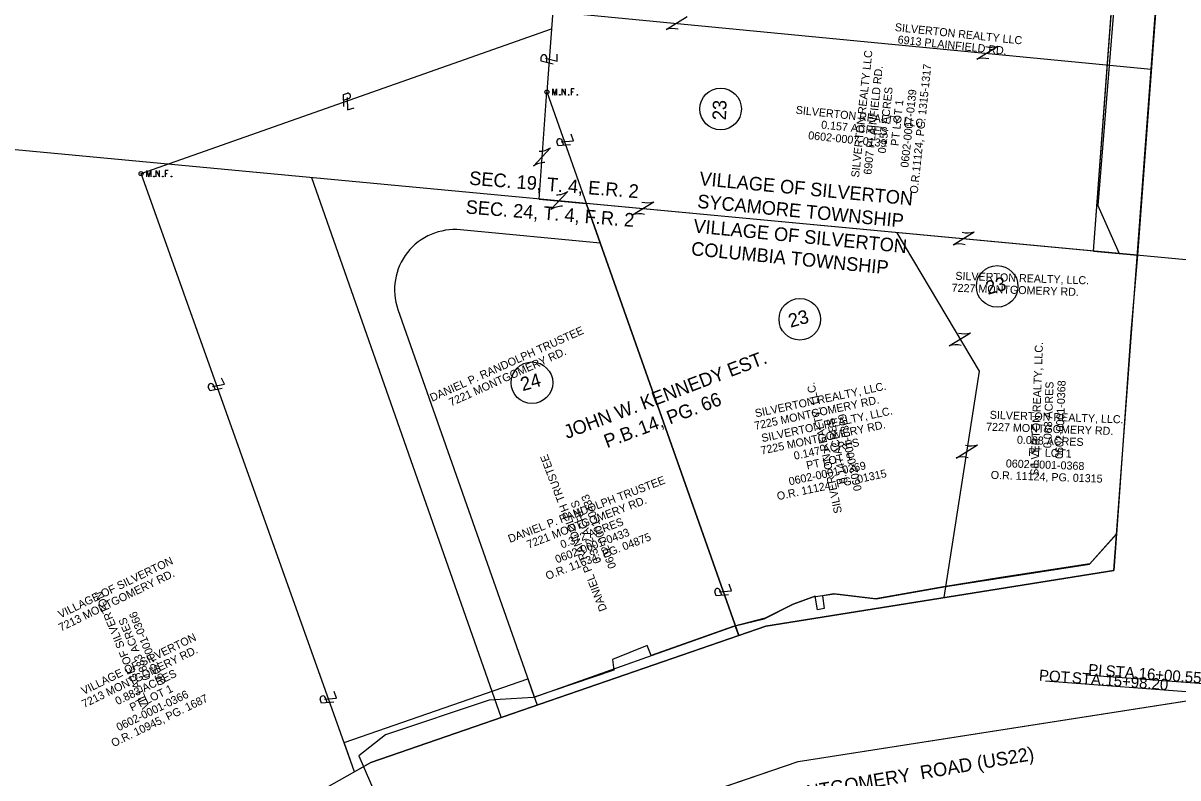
# Model space of a CAD drawing. Extents: x 204354 to 231038, y 361459 to 365260.
# Drawn here: x 220261.9 to 220550.5, y 362138.8 to 362327.5 of the extents above; entities that cross this region are included whole.
import ezdxf

# ---------------------------------------------------------------- set-up
doc = ezdxf.new("R2010")
doc.units = 0
for name, color, linetype in [('CM_Corridor_Point_Control', 7, 'Continuous'), ('CM_Corridor_Range_Conceptual', 7, 'Continuous'), ('DT_P_Contour_Minor', 7, 'Continuous'), ('DT_P_Contour_Text', 7, 'Continuous'), ('DT_P_Tie', 7, 'Continuous'), ('DT_P_Triangles', 7, 'Continuous'), ('DT_P_Void', 7, 'Continuous'), ('DT_X_Contour_Minor', 7, 'Continuous'), ('MD_P_AGB_B', 7, 'Continuous'), ('MD_P_CURB_FACE_TOP', 7, 'Continuous'), ('MD_P_Intersection_MatchLine', 7, 'Continuous'), ('MD_P_Surface_Asphalt_Concrete_Base', 7, 'Continuous'), ('MD_P_SW_BOT', 7, 'Continuous'), ('MD_P_SW_TOP', 7, 'Continuous'), ('PV_P_Walk', 7, 'Continuous'), ('SC_Shading1', 7, 'Continuous'), ('SH_Text', 7, 'Continuous')]:
    doc.layers.add(name, color=color, linetype=linetype)

msp = doc.modelspace()

# ---------------------------------------------------------------- linework, layer by layer
at = {"layer": 'CM_Corridor_Range_Conceptual'}
for p, q in [((220455.61, 362142.97), (221144.38, 362250.6)), ((220361, 362110.59), (220455.61, 362142.97))]:
    msp.add_line(p, q, dxfattribs=at)
msp.add_lwpolyline([(219371.89, 361640.54), (220361, 362110.59), (220455.61, 362142.97), (221144.38, 362250.6)], dxfattribs=at)
at = {"layer": 'DT_P_Contour_Text'}
for centre in [(220436.22, 362306.05), (220505.32, 362261.7), (220456.01, 362253.48), (220389.08, 362237.62)]:
    msp.add_circle(centre, 5.2, dxfattribs=at)
at = {"layer": 'DT_P_Tie'}
for p, q in [((220381.43, 362154.05), (220334.09, 362288.87)), ((220406.15, 362272.49), (220371.25, 362275.82)), ((220355.61, 362255.92), (220390.35, 362157))]:
    msp.add_line(p, q, dxfattribs=at)
msp.add_arc((220369.76, 362260.89), 15, 84.2977, 199.3503, dxfattribs=at)
at = {"layer": 'DT_P_Triangles'}
msp.add_lwpolyline([(220536.18, 362353), (220530.49, 362281.93), (220535.8, 362269.9), (220540.35, 362269.47), (220538.74, 362250.25), (220535.12, 362199.8), (220528.47, 362192.34), (220506.26, 362188.94), (220491.95, 362186.6), (220474.95, 362183.6), (220464.5, 362184.86), (220461.66, 362184.35), (220462.06, 362181.15), (220460.42, 362180.88), (220459.81, 362184.23), (220454.36, 362182.28), (220447.35, 362178.73), (220439.37, 362176.7), (220418.89, 362169.4), (220417.87, 362171.93), (220409.17, 362168.46), (220409.53, 362165.73), (220389.36, 362158.93), (220378.39, 362158.25), (220352.47, 362149.63), (220345.8, 362144.38), (220374.43, 362078.2)], dxfattribs=at)
at = {"layer": 'MD_P_AGB_B'}
msp.add_line((220572.38, 362161.22), (220527.51, 362164.56), dxfattribs=at)
at = {"layer": 'MD_P_CURB_FACE_TOP'}
msp.add_line((220562.24, 362159.63), (220517.36, 362162.98), dxfattribs=at)
at = {"layer": 'MD_P_Intersection_MatchLine'}
for p, q in [((220529.39, 362270.5), (220536.83, 362370.22)), ((220529.39, 362270.5), (220536.83, 362370.21)), ((220529.39, 362270.5), (220540.35, 362269.47)), ((220388.03, 362163.6), (220390.35, 362157))]:
    msp.add_line(p, q, dxfattribs=at)
at = {"layer": 'MD_P_Surface_Asphalt_Concrete_Base'}
for points in [[(220394.26, 362309.48), (220394.26, 362311.08), (220394.77, 362309.48), (220395.25, 362311.08), (220395.25, 362309.48)], [(220396.63, 362309.48), (220396.63, 362311.08), (220397.46, 362309.48), (220397.46, 362311.08)], [(220399.61, 362311.08), (220398.84, 362311.08), (220398.84, 362309.48)], [(220396.02, 362309.69), (220396.08, 362309.69), (220396.11, 362309.67), (220396.14, 362309.62), (220396.14, 362309.56), (220396.11, 362309.51), (220396.08, 362309.48), (220396.02, 362309.48), (220395.99, 362309.51), (220395.96, 362309.56), (220395.96, 362309.62), (220395.99, 362309.67), (220396.02, 362309.69)], [(220398.24, 362309.69), (220398.29, 362309.69), (220398.33, 362309.67), (220398.36, 362309.62), (220398.36, 362309.56), (220398.33, 362309.51), (220398.29, 362309.48), (220398.24, 362309.48), (220398.21, 362309.51), (220398.17, 362309.56), (220398.17, 362309.62), (220398.21, 362309.67), (220398.24, 362309.69)], [(220398.84, 362310.3), (220399.39, 362310.3)], [(220400.39, 362309.69), (220400.44, 362309.69), (220400.48, 362309.67), (220400.51, 362309.62), (220400.51, 362309.56), (220400.48, 362309.51), (220400.44, 362309.48), (220400.39, 362309.48), (220400.35, 362309.51), (220400.32, 362309.56), (220400.32, 362309.62), (220400.35, 362309.67), (220400.39, 362309.69)], [(220292.84, 362289.08), (220292.84, 362290.68), (220293.35, 362289.08), (220293.83, 362290.68), (220293.83, 362289.08)], [(220294.61, 362289.29), (220294.66, 362289.29), (220294.69, 362289.27), (220294.73, 362289.22), (220294.73, 362289.16), (220294.69, 362289.11), (220294.66, 362289.08), (220294.61, 362289.08), (220294.57, 362289.11), (220294.54, 362289.16), (220294.54, 362289.22), (220294.57, 362289.27), (220294.61, 362289.29)], [(220295.21, 362289.08), (220295.21, 362290.68), (220296.04, 362289.08), (220296.04, 362290.68)], [(220296.82, 362289.29), (220296.88, 362289.29), (220296.91, 362289.27), (220296.94, 362289.22), (220296.94, 362289.16), (220296.91, 362289.11), (220296.88, 362289.08), (220296.82, 362289.08), (220296.79, 362289.11), (220296.75, 362289.16), (220296.75, 362289.22), (220296.79, 362289.27), (220296.82, 362289.29)], [(220298.19, 362290.68), (220297.43, 362290.68), (220297.43, 362289.08)], [(220297.43, 362289.9), (220297.97, 362289.9)], [(220298.97, 362289.29), (220299.03, 362289.29), (220299.06, 362289.27), (220299.09, 362289.22), (220299.09, 362289.16), (220299.06, 362289.11), (220299.03, 362289.08), (220298.97, 362289.08), (220298.94, 362289.11), (220298.9, 362289.16), (220298.9, 362289.22), (220298.94, 362289.27), (220298.97, 362289.29)]]:
    msp.add_lwpolyline(points, dxfattribs=at)
for centre in [(220392.82, 362310.29), (220291.4, 362289.89)]:
    msp.add_circle(centre, 0.497, dxfattribs=at)
at = {"layer": 'MD_P_SW_BOT'}
for p, q in [((220398.11, 362383.18), (220392.82, 362310.29)), ((220394.27, 362330.37), (220543.82, 362315.97)), ((220422.58, 362325.89), (220427.9, 362329.17)), ((220500.2, 362318.48), (220505.52, 362321.76)), ((220502.86, 362320.12), (220502.86, 362320.12)), ((220392.79, 362317.65), (220392.76, 362318.95)), ((220393.39, 362318.47), (220393.39, 362318.47)), ((220342.01, 362308.27), (220343.25, 362308.64)), ((220390.91, 362283.53), (220392.82, 362310.29)), ((220392.82, 362310.29), (220440.76, 362174.4)), ((220342.96, 362307.9), (220342.96, 362307.9)), ((220397.08, 362296.94), (220396.64, 362298.16)), ((220397.4, 362297.9), (220397.4, 362297.9)), ((220389.44, 362291.79), (220393.72, 362296.35)), ((220391.58, 362294.07), (220391.58, 362294.07)), ((220393.81, 362280.88), (220398.08, 362285.44)), ((220390.91, 362283.53), (220402.65, 362282.42)), ((220395.94, 362283.16), (220395.94, 362283.16)), ((220540.34, 362269.47), (220402.65, 362282.42)), ((220440.76, 362174.4), (220402.71, 362282.25)), ((220414.18, 362279.58), (220419.5, 362282.86)), ((220416.84, 362281.22), (220416.84, 362281.22)), ((220494.29, 362272.05), (220499.61, 362275.32)), ((220496.95, 362273.69), (220496.95, 362273.69)), ((220493.3, 362246.84), (220498.62, 362250.12)), ((220495.96, 362248.48), (220495.96, 362248.48)), ((220310.03, 362235.85), (220309.48, 362237.02)), ((220310.26, 362236.84), (220310.26, 362236.84)), ((220495.08, 362218.8), (220500.4, 362222.08)), ((220497.74, 362220.44), (220497.74, 362220.44)), ((220436.54, 362184.5), (220436.11, 362185.72)), ((220436.86, 362185.46), (220436.86, 362185.46)), ((220337.91, 362157.65), (220337.47, 362158.87)), ((220338.23, 362158.61), (220338.23, 362158.61))]:
    msp.add_line(p, q, dxfattribs=at)
for points in [[(220344.74, 362140.37), (220291.4, 362289.89), (220393.96, 362326.05)], [(220392.43, 362318.71), (220395.4, 362318), (220395.35, 362319.75)], [(220394.4, 362317.28), (220391.41, 362317.97), (220391.38, 362319)], [(220342.06, 362306.63), (220341.97, 362309.69), (220342.96, 362309.98)], [(220342.94, 362308.9), (220343.02, 362305.84), (220344.7, 362306.33)], [(220396.4, 362297.83), (220399.45, 362298.07), (220398.87, 362299.72)], [(220398.72, 362297.07), (220395.66, 362296.82), (220395.32, 362297.8)], [(220492.04, 362183.91), (220500.91, 362240.5), (220480.35, 362275.05)], [(220311.65, 362236.15), (220308.64, 362235.59), (220308.2, 362236.53)], [(220309.27, 362236.67), (220312.29, 362237.22), (220311.54, 362238.8)], [(220435.86, 362185.39), (220438.92, 362185.63), (220438.33, 362187.28)], [(220438.18, 362184.63), (220435.12, 362184.38), (220434.78, 362185.36)], [(220339.55, 362157.79), (220336.49, 362157.53), (220336.15, 362158.5)], [(220337.23, 362158.54), (220340.28, 362158.79), (220339.7, 362160.43)]]:
    msp.add_lwpolyline(points, dxfattribs=at)
for centre, radius, start, end in [((220424.21, 362320.81), 5.34, 75.1519, 107.7944), ((220503.89, 362326.84), 5.34, 255.1519, 287.7944), ((220392.07, 362318.92), 0.69, 2.1187, 172.9759), ((220501.84, 362313.4), 5.34, 75.1519, 107.7944), ((220343.05, 362309.3), 0.69, 286.9752, 97.8324), ((220396, 362297.92), 0.69, 19.9042, 190.7613), ((220390.81, 362300.82), 5.34, 270.3758, 303.0184), ((220392.35, 362287.31), 5.34, 90.3758, 123.0184), ((220395.17, 362289.91), 5.34, 270.3758, 303.0184), ((220417.87, 362287.94), 5.34, 255.1519, 287.7944), ((220396.72, 362276.4), 5.34, 90.3758, 123.0184), ((220415.81, 362274.5), 5.34, 75.1519, 107.7944), ((220497.97, 362280.41), 5.34, 255.1519, 287.7944), ((220495.92, 362266.96), 5.34, 75.1519, 107.7944), ((220496.99, 362255.2), 5.34, 255.1519, 287.7944), ((220494.93, 362241.76), 5.34, 75.1519, 107.7944), ((220308.86, 362236.72), 0.69, 25.7397, 196.5968), ((220498.77, 362227.16), 5.34, 255.1519, 287.7944), ((220496.71, 362213.72), 5.34, 75.1519, 107.7944), ((220435.46, 362185.49), 0.69, 19.9042, 190.7613), ((220336.83, 362158.63), 0.69, 20.1022, 190.9593)]:
    msp.add_arc(centre, radius, start, end, dxfattribs=at)
at = {"layer": 'MD_P_SW_TOP'}
msp.add_line((220580.15, 362265.73), (220066.77, 362314.01), dxfattribs=at)
at = {"layer": 'PV_P_Walk'}
for p, q in [((220534.47, 362190.67), (220633.24, 363514.5)), ((220447.51, 362176.73), (220534.47, 362190.67)), ((220348.83, 362142.66), (220447.51, 362176.73)), ((220269.85, 362098.37), (220348.83, 362142.66))]:
    msp.add_line(p, q, dxfattribs=at)
at = {"layer": 'SC_Shading1'}
for points in [[(220540.35, 362269.47), (220529.39, 362270.5), (220536.83, 362370.21), (220547.79, 362369.18)], [(220534.47, 362190.67), (220447.51, 362176.73), (220440.76, 362174.4), (220439.88, 362176.89), (220447.1, 362178.59), (220454.36, 362182.28), (220459.33, 362184.06), (220464.67, 362184.85), (220475.11, 362183.61), (220492.47, 362186.7), (220528.38, 362192.25), (220535.15, 362199.84)], [(220440.76, 362174.4), (220348.83, 362142.66), (220344.74, 362140.37), (220342.12, 362147.7), (220388.03, 362163.6), (220389.64, 362159.02), (220439.88, 362176.89)]]:
    msp.add_lwpolyline(points, close=True, dxfattribs=at)
at = {"layer": 'SH_Text'}
msp.add_lwpolyline([(220534.47, 362190.67), (220447.51, 362176.73), (220440.76, 362174.4), (220439.88, 362176.89), (220447.11, 362178.59), (220454.37, 362182.28), (220459.33, 362184.07), (220464.67, 362184.86), (220475.12, 362183.61), (220492.48, 362186.7), (220528.39, 362192.25), (220535.16, 362199.84), (220534.48, 362190.67)], dxfattribs=at)
msp.add_lwpolyline([(220534.47, 362190.67), (220447.51, 362176.73), (220440.76, 362174.4), (220439.88, 362176.89), (220447.11, 362178.59), (220454.37, 362182.28), (220459.33, 362184.07), (220464.67, 362184.86), (220475.12, 362183.61), (220492.48, 362186.7), (220528.39, 362192.25), (220535.16, 362199.84), (220534.48, 362190.67)], dxfattribs=at)
msp.add_lwpolyline([(220534.47, 362190.67), (220447.51, 362176.73), (220440.76, 362174.4), (220439.88, 362176.89), (220447.11, 362178.59), (220454.37, 362182.28), (220459.33, 362184.07), (220464.67, 362184.86), (220475.12, 362183.61), (220492.48, 362186.7), (220528.39, 362192.25), (220535.16, 362199.84), (220534.48, 362190.67)], dxfattribs=at)

# ---------------------------------------------------------------- texts
at = {"layer": 'CM_Corridor_Point_Control'}
for s, rotation, p in [('SILVERTON REALTY LLC', 353.953, (220479.69, 362325.54)), ('6913 PLAINFIELD RD.', 353.953, (220480.39, 362322.45)), ('SILVERTON REALTY, LLC.', 358, (220494.85, 362263.36)), ('7227 MONTGOMERY RD.', 358, (220493.92, 362260.39)), ('DANIEL P. RANDOLPH TRUSTEE', 24.2285, (220364.14, 362232.84)), ('7221 MONTGOMERY RD.', 24.2285, (220368.88, 362231.68)), ('SILVERTON REALTY, LLC.', 12.0129, (220445.04, 362228.95)), ('7225 MONTGOMERY RD.', 12.0129, (220444.86, 362225.85)), ('VILLAGE OF SILVERTON', 25.8749, (220271.27, 362178.68)), ('7213 MONTGOMERY RD.', 25.8749, (220271.4, 362175.41))]:
    msp.add_text(s, height=2, rotation=rotation, dxfattribs=at).set_placement(p)
at = {"layer": 'DT_P_Contour_Minor'}
for s, height, rotation, p in [('SILVERTON REALTY LLC', 2, 83.953, (220470.8, 362288.84)), ('O.R.11124, PG. 1315-1317', 2, 83.953, (220485.46, 362284.8)), ('6907 PLAINFIELD RD.', 2, 83.953, (220473.89, 362289.54)), (' 0.157 ACRES', 2, 83.953, (220477.4, 362294.13)), ('0602-0007-0139', 2, 83.953, (220483.13, 362291.32)), ('PT LOT 1', 2, 83.953, (220480.69, 362296.72)), ('SEC. 19, T. 4, E.R. 2', 3.4, 355.407, (220373.3, 362287.13)), ('VILLAGE OF SILVERTON', 3.4, 354.5316, (220430.81, 362287.02)), ('SEC. 24, T. 4, F.R. 2', 3.4, 355.407, (220372.43, 362279.93)), ('SYCAMORE TOWNSHIP', 3.4, 354.5316, (220430.27, 362281.34)), ('VILLAGE OF SILVERTON', 3.4, 354.4298, (220429.3, 362275.19)), ('COLUMBIA TOWNSHIP', 3.4, 354.4298, (220428.74, 362269.51)), (' JOHN W. KENNEDY EST.', 3.4, 20.7325, (220396.64, 362223.09)), ('14, PG. 66', 3.4, 20.7325, (220416.43, 362224.48)), ('SILVERTON REALTY, LLC.', 2, 12.0129, (220446.63, 362222.76)), ('SILVERTON REALTY, LLC.', 2, 358, (220503.45, 362228.62)), ('7225 MONTGOMERY RD.', 2, 12.0129, (220446.46, 362219.65)), ('7227 MONTGOMERY RD.', 2, 358, (220502.53, 362225.65)), (' P.B.', 3.4, 20.7325, (220406.67, 362220.79)), ('0.147 ACRES', 2, 12.0129, (220454.73, 362218.35)), ('0.088 ACRES', 2, 358, (220510.24, 362222.38)), ('PT LOT 1', 2, 12.0129, (220457.86, 362215.94)), ('PT LOT1 ', 2, 358, (220513.05, 362219.28)), ('O.R. 11124, PG. 01315', 2, 12.0129, (220450.5, 362208.24)), ('0602-0001-0369', 2, 12.0129, (220453.48, 362211.95)), ('0602-0001-0368', 2, 358, (220507.46, 362216.47)), ('DANIEL P. RANDOLPH TRUSTEE', 2, 20.9545, (220383.57, 362197.57)), ('O.R. 11124, PG. 01315', 2, 358, (220503.69, 362213.6)), ('7221 MONTGOMERY RD.', 2, 20.9545, (220388.25, 362196.15)), ('0.372 ACRES', 2, 20.9545, (220396.62, 362196.15)), ('O.R. 11634, PG. 04875', 2, 20.9545, (220392.94, 362188.31)), ('0602-0001-0433', 2, 20.9545, (220395.33, 362192.44)), ('VILLAGE OF SILVERTON', 2, 25.8749, (220277.05, 362159.56)), ('7213 MONTGOMERY RD.', 2, 25.8749, (220277.19, 362156.29)), ('0.883 ACRES', 2, 25.8749, (220285.53, 362157)), ('PT LOT 1', 2, 25.8749, (220289.14, 362155.42)), ('O.R. 10945, PG. 1687', 2, 25.8749, (220284.54, 362146.51)), ('0602-0001-0366', 2, 25.8749, (220285.83, 362150.48))]:
    msp.add_text(s, height=height, rotation=rotation, dxfattribs=at).set_placement(p)
at = {"layer": 'DT_P_Contour_Text'}
for s, rotation, p in [('23', 88.3143, (220437.56, 362303.2)), ('23', 15.6676, (220503, 362259.58)), ('23', 15.6676, (220453.68, 362251.35)), ('24', 15.6676, (220386.75, 362235.49))]:
    msp.add_text(s, height=3.4, rotation=rotation, dxfattribs=at).set_placement(p)
at = {"layer": 'DT_P_Void'}
msp.add_text(' MONTGOMERY  ROAD (US22)', height=3.4, rotation=9.7476, dxfattribs=at).set_placement((220449.53, 362132.12))
at = {"layer": 'DT_X_Contour_Minor'}
for s, rotation, p in [('SILVERTON REALTY LLC', 353.953, (220454.92, 362304.87)), (' 0.157 ACRES', 353.953, (220460.53, 362301.26)), ('0602-0007-0139', 353.953, (220458.03, 362298.51)), ('SILVERTON REALTY, LLC.', 88, (220515.6, 362214.34)), ('SILVERTON REALTY, LLC.', 102.0129, (220466.57, 362205.19)), ('0.088 ACRES', 88, (220518.84, 362221.23)), ('0602-0001-0368', 88, (220521.75, 362218.55)), ('0.147 ACRES', 102.0129, (220468.05, 362212.66)), ('0602-0001-0369', 102.0129, (220471.52, 362210.79)), ('DANIEL P. RANDOLPH TRUSTEE', 110.9545, (220407.87, 362180.91)), ('0.372 ACRES', 110.9545, (220406.5, 362192.89)), ('0602-0001-0433', 110.9545, (220410.2, 362191.59)), ('VILLAGE OF SILVERTON', 112.2601, (220293.56, 362156.56)), ('0.883 ACRES', 112.2601, (220293.87, 362163.72)), ('0602-0001-0366', 112.2601, (220297.62, 362162.48))]:
    msp.add_text(s, height=2, rotation=rotation, dxfattribs=at).set_placement(p)
at = {"layer": 'MD_P_AGB_B'}
for s, p in [('PI', (220527.99, 362164.56)), (' STA. ', (220531.3, 362164.32)), ('16+00.55', (220540.6, 362163.62))]:
    msp.add_text(s, height=2.8, rotation=355.7333, dxfattribs=at).set_placement(p)
at = {"layer": 'MD_P_CURB_FACE_TOP'}
for s, p in [('POT', (220515.69, 362163.14)), (' STA. ', (220522.87, 362162.61)), ('15+98.20', (220532.29, 362161.91))]:
    msp.add_text(s, height=2.8, rotation=355.7333, dxfattribs=at).set_placement(p)

doc.saveas('drawing.dxf')
